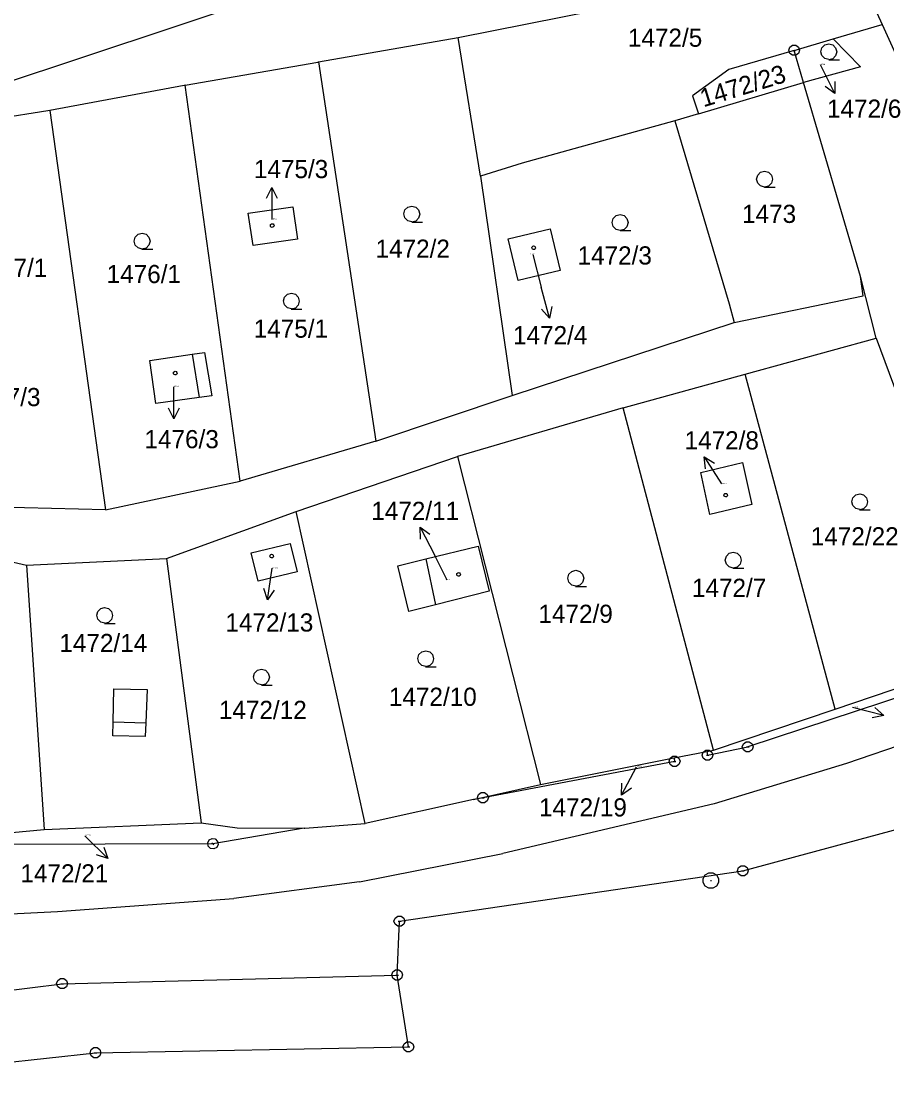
# Model space of a CAD drawing. Extents: x -806774 to -803680, y -1151731 to -1150053.
# Drawn here: x -805196.8 to -805115.9, y -1150674.1 to -1150574.5 of the extents above; entities that cross this region are included whole.
import ezdxf

# ---------------------------------------------------------------- set-up
doc = ezdxf.new("R2010")
doc.units = 0
for name, color, linetype in [('1', 7, 'Continuous'), ('12', 7, 'Continuous'), ('2', 7, 'Continuous'), ('3', 7, 'Continuous'), ('4', 7, 'Continuous'), ('5', 7, 'Continuous'), ('6', 7, 'Continuous'), ('7', 7, 'Continuous'), ('8', 7, 'Continuous')]:
    doc.layers.add(name, color=color, linetype=linetype)

msp = doc.modelspace()

# ---------------------------------------------------------------- linework, layer by layer
at = {"layer": '1'}
for p, q in [((-805123.35, -1150559.31), (-805116.35, -1150574.79)), ((-805156, -1150576), (-805143.08, -1150573.46)), ((-805120.93, -1150576.14), (-805116.35, -1150574.79)), ((-805116.35, -1150574.79), (-805108.82, -1150591.44)), ((-805169.07, -1150578.3), (-805156, -1150576)), ((-805153.92, -1150588.97), (-805156, -1150576)), ((-805124.58, -1150577.22), (-805120.93, -1150576.14)), ((-805120.93, -1150576.14), (-805118.36, -1150578.76)), ((-805124.58, -1150577.22), (-805130.69, -1150579.02)), ((-805123.7, -1150580.21), (-805124.58, -1150577.22)), ((-805181.51, -1150580.47), (-805169.12, -1150578.31)), ((-805169.12, -1150578.31), (-805169.07, -1150578.3)), ((-805169.07, -1150578.3), (-805163.68, -1150613.78)), ((-805130.69, -1150579.02), (-805134.09, -1150581.46)), ((-805118.36, -1150578.76), (-805123.7, -1150580.21)), ((-805181.63, -1150580.5), (-805194.17, -1150582.84)), ((-805181.51, -1150580.47), (-805181.63, -1150580.5)), ((-805176.39, -1150617.53), (-805181.51, -1150580.47)), ((-805133.51, -1150583.16), (-805123.7, -1150580.21)), ((-805118.39, -1150598.36), (-805123.7, -1150580.21)), ((-805134.09, -1150581.46), (-805133.51, -1150583.16)), ((-805194.37, -1150582.88), (-805206.79, -1150584.83)), ((-805194.17, -1150582.84), (-805194.37, -1150582.88)), ((-805194.17, -1150582.84), (-805188.96, -1150620.19)), ((-805133.51, -1150583.16), (-805135.74, -1150583.81)), ((-805135.74, -1150583.81), (-805150, -1150587.78)), ((-805135.74, -1150583.81), (-805130.67, -1150600.93)), ((-805150, -1150587.78), (-805153.92, -1150588.97)), ((-805153.92, -1150588.97), (-805150.96, -1150609.51)), ((-805175.62, -1150592.44), (-805171.46, -1150591.84)), ((-805171.46, -1150591.84), (-805171.01, -1150594.89)), ((-805175.17, -1150595.46), (-805175.62, -1150592.44)), ((-805151.32, -1150594.85), (-805147.39, -1150593.91)), ((-805147.39, -1150593.91), (-805146.46, -1150597.81)), ((-805171.01, -1150594.89), (-805175.17, -1150595.46)), ((-805150.39, -1150598.75), (-805151.32, -1150594.85)), ((-805146.46, -1150597.81), (-805150.39, -1150598.75)), ((-805118.12, -1150600.19), (-805118.39, -1150598.36)), ((-805116.91, -1150604.14), (-805118.39, -1150598.36)), ((-805130.67, -1150600.93), (-805130.18, -1150602.69)), ((-805130.18, -1150602.69), (-805118.12, -1150600.19)), ((-805150.96, -1150609.51), (-805130.18, -1150602.69)), ((-805129.15, -1150607.51), (-805116.91, -1150604.14)), ((-805116.91, -1150604.14), (-805113.43, -1150613.57)), ((-805184.82, -1150606.24), (-805180.87, -1150605.65)), ((-805180.87, -1150605.65), (-805179.73, -1150605.48)), ((-805179.73, -1150605.48), (-805179.03, -1150609.54)), ((-805184.28, -1150610.26), (-805184.82, -1150606.24)), ((-805140.56, -1150610.66), (-805129.15, -1150607.51)), ((-805120.75, -1150638.84), (-805129.15, -1150607.51)), ((-805180.2, -1150609.7), (-805184.28, -1150610.26)), ((-805179.03, -1150609.54), (-805180.2, -1150609.7)), ((-805163.68, -1150613.78), (-805150.96, -1150609.51)), ((-805140.56, -1150610.66), (-805156.07, -1150615.2)), ((-805132.12, -1150642.68), (-805140.56, -1150610.66)), ((-805163.68, -1150613.78), (-805176.39, -1150617.53)), ((-805171.14, -1150620.35), (-805156.07, -1150615.2)), ((-805156.07, -1150615.2), (-805148.29, -1150645.9)), ((-805133.32, -1150616.71), (-805129.41, -1150615.78)), ((-805129.41, -1150615.78), (-805128.54, -1150619.71)), ((-805132.45, -1150620.65), (-805133.32, -1150616.71)), ((-805188.96, -1150620.19), (-805176.39, -1150617.53)), ((-805188.96, -1150620.19), (-805202.04, -1150619.89)), ((-805128.54, -1150619.71), (-805132.45, -1150620.65)), ((-805183.26, -1150624.76), (-805171.14, -1150620.35)), ((-805164.69, -1150649.54), (-805171.14, -1150620.35)), ((-805209.21, -1150622.35), (-805196.37, -1150625.39)), ((-805175.35, -1150624.23), (-805171.71, -1150623.34)), ((-805171.71, -1150623.34), (-805171.06, -1150625.99)), ((-805159.01, -1150624.79), (-805154.14, -1150623.59)), ((-805154.14, -1150623.59), (-805153.1, -1150627.82)), ((-805196.37, -1150625.39), (-805183.26, -1150624.76)), ((-805183.26, -1150624.76), (-805180.04, -1150649.49)), ((-805174.7, -1150626.88), (-805175.35, -1150624.23)), ((-805161.65, -1150625.43), (-805159.01, -1150624.79)), ((-805196.37, -1150625.39), (-805194.7, -1150650.11)), ((-805171.06, -1150625.99), (-805174.7, -1150626.88)), ((-805160.61, -1150629.72), (-805161.65, -1150625.43)), ((-805153.1, -1150627.82), (-805158.11, -1150629.09)), ((-805158.11, -1150629.09), (-805160.61, -1150629.72)), ((-805105.89, -1150634.79), (-805128.92, -1150642.38)), ((-805120.75, -1150638.84), (-805107.03, -1150634.2)), ((-805132.12, -1150642.68), (-805120.75, -1150638.84)), ((-805135.82, -1150643.41), (-805132.75, -1150642.8)), ((-805132.75, -1150642.8), (-805132.12, -1150642.68)), ((-805132.75, -1150642.8), (-805132.67, -1150643.17)), ((-805132.67, -1150643.17), (-805128.92, -1150642.38)), ((-805135.75, -1150643.74), (-805153.67, -1150647.14)), ((-805148.29, -1150645.9), (-805135.82, -1150643.41)), ((-805135.82, -1150643.41), (-805135.75, -1150643.74)), ((-805154.57, -1150647.29), (-805148.29, -1150645.9)), ((-805154.57, -1150647.29), (-805164.69, -1150649.54)), ((-805153.67, -1150647.14), (-805154.57, -1150647.29)), ((-805129.38, -1150653.98), (-805107.63, -1150648.08)), ((-805194.7, -1150650.11), (-805180.04, -1150649.49)), ((-805180.04, -1150649.49), (-805176.67, -1150649.94)), ((-805170.32, -1150649.99), (-805164.69, -1150649.54)), ((-805209.44, -1150651.45), (-805194.7, -1150650.11)), ((-805170.38, -1150650), (-805178.93, -1150651.45)), ((-805176.67, -1150649.94), (-805170.38, -1150650)), ((-805170.38, -1150650), (-805170.32, -1150649.99)), ((-805178.93, -1150651.45), (-805208.17, -1150651.53)), ((-805161.49, -1150658.69), (-805129.38, -1150653.98)), ((-805161.69, -1150663.73), (-805161.49, -1150658.69)), ((-805193.03, -1150664.54), (-805161.69, -1150663.73)), ((-805160.65, -1150670.45), (-805161.69, -1150663.73)), ((-805220.59, -1150668.04), (-805193.03, -1150664.54)), ((-805189.9, -1150671), (-805160.65, -1150670.45)), ((-805218.5, -1150674.08), (-805189.9, -1150671))]:
    msp.add_line(p, q, dxfattribs=at)
at = {"layer": '12'}
for p, q in [((-805175.62, -1150592.44), (-805171.46, -1150591.84)), ((-805171.46, -1150591.84), (-805171.01, -1150594.89)), ((-805175.17, -1150595.46), (-805175.62, -1150592.44)), ((-805151.32, -1150594.85), (-805147.39, -1150593.91)), ((-805147.39, -1150593.91), (-805146.46, -1150597.81)), ((-805171.01, -1150594.89), (-805175.17, -1150595.46)), ((-805150.39, -1150598.75), (-805151.32, -1150594.85)), ((-805146.46, -1150597.81), (-805150.39, -1150598.75)), ((-805184.82, -1150606.24), (-805180.87, -1150605.65)), ((-805180.87, -1150605.65), (-805180.2, -1150609.7)), ((-805184.28, -1150610.26), (-805184.82, -1150606.24)), ((-805180.2, -1150609.7), (-805184.28, -1150610.26)), ((-805133.32, -1150616.71), (-805129.41, -1150615.78)), ((-805129.41, -1150615.78), (-805128.54, -1150619.71)), ((-805132.45, -1150620.65), (-805133.32, -1150616.71)), ((-805128.54, -1150619.71), (-805132.45, -1150620.65)), ((-805175.35, -1150624.23), (-805171.71, -1150623.34)), ((-805171.71, -1150623.34), (-805171.06, -1150625.99)), ((-805159.01, -1150624.79), (-805154.14, -1150623.59)), ((-805154.14, -1150623.59), (-805153.1, -1150627.82)), ((-805174.7, -1150626.88), (-805175.35, -1150624.23)), ((-805159.01, -1150624.79), (-805158.11, -1150629.09)), ((-805171.06, -1150625.99), (-805174.7, -1150626.88)), ((-805153.1, -1150627.82), (-805158.11, -1150629.09))]:
    msp.add_line(p, q, dxfattribs=at)
at = {"layer": '3'}
for points in [[(-805121.33, -1150578.08), (-805121.71, -1150577.98), (-805121.98, -1150577.71), (-805122.08, -1150577.34), (-805121.98, -1150576.97), (-805121.71, -1150576.7), (-805121.34, -1150576.6), (-805120.97, -1150576.7), (-805120.7, -1150576.97), (-805120.6, -1150577.35), (-805120.7, -1150577.73), (-805120.97, -1150578), (-805121.35, -1150578.1), (-805120.35, -1150578.1)], [(-805127.34, -1150590), (-805127.72, -1150589.9), (-805127.99, -1150589.63), (-805128.09, -1150589.26), (-805127.99, -1150588.89), (-805127.72, -1150588.62), (-805127.35, -1150588.52), (-805126.98, -1150588.62), (-805126.71, -1150588.89), (-805126.61, -1150589.27), (-805126.71, -1150589.65), (-805126.98, -1150589.92), (-805127.36, -1150590.02), (-805126.36, -1150590.02)], [(-805160.32, -1150593.26), (-805160.7, -1150593.16), (-805160.97, -1150592.89), (-805161.07, -1150592.52), (-805160.97, -1150592.15), (-805160.7, -1150591.88), (-805160.33, -1150591.78), (-805159.96, -1150591.88), (-805159.69, -1150592.15), (-805159.59, -1150592.53), (-805159.69, -1150592.91), (-805159.96, -1150593.18), (-805160.34, -1150593.28), (-805159.34, -1150593.28)], [(-805140.84, -1150594.06), (-805141.22, -1150593.96), (-805141.49, -1150593.69), (-805141.59, -1150593.32), (-805141.49, -1150592.95), (-805141.22, -1150592.68), (-805140.85, -1150592.58), (-805140.48, -1150592.68), (-805140.21, -1150592.95), (-805140.11, -1150593.33), (-805140.21, -1150593.71), (-805140.48, -1150593.98), (-805140.86, -1150594.08), (-805139.86, -1150594.08)], [(-805185.54, -1150595.8), (-805185.92, -1150595.7), (-805186.19, -1150595.43), (-805186.29, -1150595.06), (-805186.19, -1150594.69), (-805185.92, -1150594.42), (-805185.55, -1150594.32), (-805185.18, -1150594.42), (-805184.91, -1150594.69), (-805184.81, -1150595.07), (-805184.91, -1150595.45), (-805185.18, -1150595.72), (-805185.56, -1150595.82), (-805184.56, -1150595.82)], [(-805171.58, -1150601.4), (-805171.96, -1150601.3), (-805172.23, -1150601.03), (-805172.33, -1150600.66), (-805172.23, -1150600.29), (-805171.96, -1150600.02), (-805171.59, -1150599.92), (-805171.22, -1150600.02), (-805170.95, -1150600.29), (-805170.85, -1150600.67), (-805170.95, -1150601.05), (-805171.22, -1150601.32), (-805171.6, -1150601.42), (-805170.6, -1150601.42)], [(-805118.44, -1150620.18), (-805118.82, -1150620.08), (-805119.09, -1150619.81), (-805119.19, -1150619.44), (-805119.09, -1150619.07), (-805118.82, -1150618.8), (-805118.45, -1150618.7), (-805118.08, -1150618.8), (-805117.81, -1150619.07), (-805117.71, -1150619.45), (-805117.81, -1150619.83), (-805118.08, -1150620.1), (-805118.46, -1150620.2), (-805117.46, -1150620.2)], [(-805130.27, -1150625.65), (-805130.65, -1150625.55), (-805130.92, -1150625.28), (-805131.02, -1150624.91), (-805130.92, -1150624.54), (-805130.65, -1150624.27), (-805130.28, -1150624.17), (-805129.91, -1150624.27), (-805129.64, -1150624.54), (-805129.54, -1150624.92), (-805129.64, -1150625.3), (-805129.91, -1150625.57), (-805130.29, -1150625.67), (-805129.29, -1150625.67)], [(-805144.99, -1150627.34), (-805145.37, -1150627.24), (-805145.64, -1150626.97), (-805145.74, -1150626.6), (-805145.64, -1150626.23), (-805145.37, -1150625.96), (-805145, -1150625.86), (-805144.63, -1150625.96), (-805144.36, -1150626.23), (-805144.26, -1150626.61), (-805144.36, -1150626.99), (-805144.63, -1150627.26), (-805145.01, -1150627.36), (-805144.01, -1150627.36)], [(-805189.04, -1150630.81), (-805189.42, -1150630.71), (-805189.69, -1150630.44), (-805189.79, -1150630.07), (-805189.69, -1150629.7), (-805189.42, -1150629.43), (-805189.05, -1150629.33), (-805188.68, -1150629.43), (-805188.41, -1150629.7), (-805188.31, -1150630.08), (-805188.41, -1150630.46), (-805188.68, -1150630.73), (-805189.06, -1150630.83), (-805188.06, -1150630.83)], [(-805159.02, -1150634.86), (-805159.4, -1150634.76), (-805159.67, -1150634.49), (-805159.77, -1150634.12), (-805159.67, -1150633.75), (-805159.4, -1150633.48), (-805159.03, -1150633.38), (-805158.66, -1150633.48), (-805158.39, -1150633.75), (-805158.29, -1150634.13), (-805158.39, -1150634.51), (-805158.66, -1150634.78), (-805159.04, -1150634.88), (-805158.04, -1150634.88)], [(-805174.38, -1150636.58), (-805174.76, -1150636.48), (-805175.03, -1150636.21), (-805175.13, -1150635.84), (-805175.03, -1150635.47), (-805174.76, -1150635.2), (-805174.39, -1150635.1), (-805174.02, -1150635.2), (-805173.75, -1150635.47), (-805173.65, -1150635.85), (-805173.75, -1150636.23), (-805174.02, -1150636.5), (-805174.4, -1150636.6), (-805173.4, -1150636.6)]]:
    msp.add_lwpolyline(points, dxfattribs=at)
at = {"layer": '4'}
for p, q in [((-805180.87, -1150605.65), (-805180.2, -1150609.7)), ((-805159.01, -1150624.79), (-805158.11, -1150629.09)), ((-805188.25, -1150640.05), (-805188.19, -1150636.96)), ((-805188.19, -1150636.96), (-805185.08, -1150637)), ((-805185.08, -1150637), (-805185.2, -1150640.13)), ((-805188.28, -1150641.34), (-805188.25, -1150640.05)), ((-805188.25, -1150640.05), (-805185.2, -1150640.13)), ((-805185.2, -1150640.13), (-805185.26, -1150641.41)), ((-805185.26, -1150641.41), (-805188.28, -1150641.34))]:
    msp.add_line(p, q, dxfattribs=at)
at = {"layer": '5'}
for points in [[(-805173.38, -1150593.44), (-805173.28, -1150593.46), (-805173.23, -1150593.55), (-805173.21, -1150593.61), (-805173.23, -1150593.7), (-805173.31, -1150593.77), (-805173.38, -1150593.78), (-805173.47, -1150593.75), (-805173.53, -1150593.69), (-805173.55, -1150593.61), (-805173.53, -1150593.52), (-805173.45, -1150593.45)], [(-805148.94, -1150595.51), (-805148.84, -1150595.53), (-805148.79, -1150595.62), (-805148.77, -1150595.68), (-805148.79, -1150595.77), (-805148.87, -1150595.84), (-805148.94, -1150595.85), (-805149.03, -1150595.82), (-805149.09, -1150595.76), (-805149.11, -1150595.68), (-805149.09, -1150595.59), (-805149.01, -1150595.52)], [(-805182.45, -1150607.24), (-805182.35, -1150607.26), (-805182.3, -1150607.35), (-805182.28, -1150607.41), (-805182.3, -1150607.5), (-805182.38, -1150607.57), (-805182.45, -1150607.58), (-805182.54, -1150607.55), (-805182.6, -1150607.49), (-805182.62, -1150607.41), (-805182.6, -1150607.32), (-805182.52, -1150607.25)], [(-805130.98, -1150618.66), (-805130.88, -1150618.68), (-805130.83, -1150618.77), (-805130.81, -1150618.83), (-805130.83, -1150618.92), (-805130.91, -1150618.99), (-805130.98, -1150619), (-805131.07, -1150618.97), (-805131.13, -1150618.91), (-805131.15, -1150618.83), (-805131.13, -1150618.74), (-805131.05, -1150618.67)], [(-805173.44, -1150624.36), (-805173.34, -1150624.38), (-805173.29, -1150624.47), (-805173.27, -1150624.53), (-805173.29, -1150624.62), (-805173.37, -1150624.69), (-805173.44, -1150624.7), (-805173.53, -1150624.67), (-805173.59, -1150624.61), (-805173.61, -1150624.53), (-805173.59, -1150624.44), (-805173.51, -1150624.37)], [(-805155.96, -1150626.08), (-805155.86, -1150626.1), (-805155.81, -1150626.19), (-805155.79, -1150626.25), (-805155.81, -1150626.34), (-805155.89, -1150626.41), (-805155.96, -1150626.42), (-805156.05, -1150626.39), (-805156.11, -1150626.33), (-805156.13, -1150626.25), (-805156.11, -1150626.16), (-805156.03, -1150626.09)]]:
    msp.add_lwpolyline(points, close=True, dxfattribs=at)
at = {"layer": '6'}
for p, q in [((-805267.37, -1150603.37), (-805132.32, -1150558.17)), ((-805104.02, -1150638.5), (-805119.69, -1150643.95)), ((-805119.69, -1150643.95), (-805132.06, -1150647.7)), ((-805132.06, -1150647.7), (-805151.83, -1150652.34)), ((-805165.22, -1150655), (-805151.83, -1150652.34)), ((-805165.22, -1150655), (-805176.96, -1150656.55)), ((-805193.46, -1150657.79), (-805176.96, -1150656.55)), ((-805221.49, -1150659.08), (-805193.46, -1150657.79))]:
    msp.add_line(p, q, dxfattribs=at)
at = {"layer": '7'}
for p, q in [((-805120.779, -1150581.254), (-805122.12, -1150578.57)), ((-805173.42, -1150590.04), (-805173.42, -1150593.04)), ((-805149.02, -1150596.3), (-805148.22, -1150599.38)), ((-805147.468, -1150602.284), (-805148.22, -1150599.38)), ((-805182.579, -1150611.7), (-805182.58, -1150608.7)), ((-805132.996, -1150615.259), (-805131.37, -1150617.78)), ((-805159.537, -1150621.819), (-805158.17, -1150624.49)), ((-805157.01, -1150626.78), (-805158.17, -1150624.49)), ((-805173.834, -1150628.637), (-805173.39, -1150625.67)), ((-805116.2, -1150639.429), (-805119.11, -1150638.7)), ((-805140.713, -1150646.902), (-805139.31, -1150644.25)), ((-805188.769, -1150652.821), (-805190.89, -1150650.7))]:
    msp.add_line(p, q, dxfattribs=at)
for points in [[(-805120.779, -1150580.136), (-805120.779, -1150581.254), (-805121.673, -1150580.583)], [(-805173.92, -1150591.04), (-805173.42, -1150590.04), (-805172.92, -1150591.04)], [(-805147.235, -1150601.191), (-805147.468, -1150602.284), (-805148.203, -1150601.441)], [(-805182.079, -1150610.7), (-805182.579, -1150611.7), (-805183.079, -1150610.7)], [(-805132.874, -1150616.371), (-805132.996, -1150615.259), (-805132.034, -1150615.828)], [(-805159.526, -1150622.937), (-805159.537, -1150621.819), (-805158.636, -1150622.482)], [(-805173.192, -1150627.722), (-805173.834, -1150628.637), (-805174.181, -1150627.574)], [(-805117.048, -1150638.701), (-805116.2, -1150639.429), (-805117.291, -1150639.671)], [(-805139.803, -1150646.252), (-805140.713, -1150646.902), (-805140.687, -1150645.784)], [(-805189.122, -1150651.761), (-805188.769, -1150652.821), (-805189.829, -1150652.468)]]:
    msp.add_lwpolyline(points, dxfattribs=at)
at = {"layer": '8'}
for p, q in [((-805124.7, -1150577.22), (-805124.46, -1150577.22)), ((-805129.04, -1150642.38), (-805128.8, -1150642.38)), ((-805135.87, -1150643.74), (-805135.63, -1150643.74)), ((-805132.79, -1150643.17), (-805132.55, -1150643.17)), ((-805153.79, -1150647.14), (-805153.55, -1150647.14)), ((-805179.015, -1150651.365), (-805178.845, -1150651.535)), ((-805132.41, -1150654.87), (-805132.31, -1150654.87)), ((-805129.5, -1150653.98), (-805129.26, -1150653.98)), ((-805161.61, -1150658.69), (-805161.37, -1150658.69)), ((-805161.81, -1150663.73), (-805161.57, -1150663.73)), ((-805193.15, -1150664.54), (-805192.91, -1150664.54)), ((-805160.77, -1150670.45), (-805160.53, -1150670.45)), ((-805190.02, -1150671), (-805189.78, -1150671))]:
    msp.add_line(p, q, dxfattribs=at)
for points in [[(-805124.43, -1150576.74), (-805124.18, -1150576.92), (-805124.08, -1150577.21), (-805124.18, -1150577.5), (-805124.43, -1150577.68), (-805124.74, -1150577.68), (-805124.99, -1150577.5), (-805125.09, -1150577.21), (-805124.99, -1150576.92), (-805124.74, -1150576.74)], [(-805128.77, -1150641.9), (-805128.52, -1150642.08), (-805128.42, -1150642.37), (-805128.52, -1150642.66), (-805128.77, -1150642.84), (-805129.08, -1150642.84), (-805129.33, -1150642.66), (-805129.43, -1150642.37), (-805129.33, -1150642.08), (-805129.08, -1150641.9)], [(-805132.52, -1150642.69), (-805132.27, -1150642.87), (-805132.17, -1150643.16), (-805132.27, -1150643.45), (-805132.52, -1150643.63), (-805132.83, -1150643.63), (-805133.08, -1150643.45), (-805133.18, -1150643.16), (-805133.08, -1150642.87), (-805132.83, -1150642.69)], [(-805135.6, -1150643.26), (-805135.35, -1150643.44), (-805135.25, -1150643.73), (-805135.35, -1150644.02), (-805135.6, -1150644.2), (-805135.91, -1150644.2), (-805136.16, -1150644.02), (-805136.26, -1150643.73), (-805136.16, -1150643.44), (-805135.91, -1150643.26)], [(-805153.52, -1150646.66), (-805153.27, -1150646.84), (-805153.17, -1150647.13), (-805153.27, -1150647.42), (-805153.52, -1150647.6), (-805153.83, -1150647.6), (-805154.08, -1150647.42), (-805154.18, -1150647.13), (-805154.08, -1150646.84), (-805153.83, -1150646.66)], [(-805178.485, -1150651.217), (-805178.435, -1150651.521), (-805178.569, -1150651.796), (-805178.845, -1150651.931), (-805179.149, -1150651.881), (-805179.368, -1150651.662), (-805179.418, -1150651.358), (-805179.284, -1150651.082), (-805179.008, -1150650.948), (-805178.704, -1150650.997)], [(-805129.23, -1150653.5), (-805128.98, -1150653.68), (-805128.88, -1150653.97), (-805128.98, -1150654.26), (-805129.23, -1150654.44), (-805129.54, -1150654.44), (-805129.79, -1150654.26), (-805129.89, -1150653.97), (-805129.79, -1150653.68), (-805129.54, -1150653.5)], [(-805132.17, -1150654.15), (-805131.83, -1150654.34), (-805131.64, -1150654.68), (-805131.64, -1150655.07), (-805131.83, -1150655.41), (-805132.17, -1150655.6), (-805132.56, -1150655.6), (-805132.9, -1150655.41), (-805133.09, -1150655.07), (-805133.09, -1150654.68), (-805132.9, -1150654.34), (-805132.56, -1150654.15)], [(-805161.34, -1150658.21), (-805161.09, -1150658.39), (-805160.99, -1150658.68), (-805161.09, -1150658.97), (-805161.34, -1150659.15), (-805161.65, -1150659.15), (-805161.9, -1150658.97), (-805162, -1150658.68), (-805161.9, -1150658.39), (-805161.65, -1150658.21)], [(-805161.54, -1150663.25), (-805161.29, -1150663.43), (-805161.19, -1150663.72), (-805161.29, -1150664.01), (-805161.54, -1150664.19), (-805161.85, -1150664.19), (-805162.1, -1150664.01), (-805162.2, -1150663.72), (-805162.1, -1150663.43), (-805161.85, -1150663.25)], [(-805192.88, -1150664.06), (-805192.63, -1150664.24), (-805192.53, -1150664.53), (-805192.63, -1150664.82), (-805192.88, -1150665), (-805193.19, -1150665), (-805193.44, -1150664.82), (-805193.54, -1150664.53), (-805193.44, -1150664.24), (-805193.19, -1150664.06)], [(-805189.75, -1150670.52), (-805189.5, -1150670.7), (-805189.4, -1150670.99), (-805189.5, -1150671.28), (-805189.75, -1150671.46), (-805190.06, -1150671.46), (-805190.31, -1150671.28), (-805190.41, -1150670.99), (-805190.31, -1150670.7), (-805190.06, -1150670.52)], [(-805160.5, -1150669.97), (-805160.25, -1150670.15), (-805160.15, -1150670.44), (-805160.25, -1150670.73), (-805160.5, -1150670.91), (-805160.81, -1150670.91), (-805161.06, -1150670.73), (-805161.16, -1150670.44), (-805161.06, -1150670.15), (-805160.81, -1150669.97)]]:
    msp.add_lwpolyline(points, close=True, dxfattribs=at)

# ---------------------------------------------------------------- texts
at = {"layer": '2'}
for s, height, p in [('1472/5', 1.7, (-805140.125, -1150576.88)), ('1472/6', 0.1, (-805122.097, -1150578.57)), ('1473', 1.7, (-805129.452, -1150593.36)), ('1475/3', 0.1, (-805173.397, -1150593.04)), ('1472/2', 1.7, (-805163.722, -1150596.62)), ('1472/3', 1.7, (-805144.835, -1150597.25)), ('1477/1', 1.7, (-805201.366, -1150598.41)), ('1472/4', 0.1, (-805149.244, -1150596.3)), ('1476/1', 1.7, (-805188.866, -1150598.99)), ('1475/1', 1.7, (-805175.113, -1150604.1)), ('1476/3', 0.1, (-805182.557, -1150608.7)), ('1472/8', 0.1, (-805131.347, -1150617.78)), ('1472/22', 1.7, (-805123.024, -1150623.53)), ('1472/13', 0.1, (-805173.367, -1150625.67)), ('1472/11', 0.1, (-805157.234, -1150626.78)), ('1472/7', 1.7, (-805134.138, -1150628.35)), ('1472/9', 1.7, (-805148.488, -1150630.78)), ('1472/14', 1.7, (-805193.289, -1150633.51)), ('1472/10', 1.7, (-805162.476, -1150638.54)), ('1472/12', 1.7, (-805178.373, -1150639.77)), ('1472/20', 0.1, (-805119.087, -1150638.7)), ('1472/19', 0.1, (-805139.287, -1150644.25)), ('1472/21', 0.1, (-805190.867, -1150650.7))]:
    msp.add_text(s, height=height, dxfattribs=at).set_placement(p)
msp.add_text('1472/23', height=1.7, rotation=17.07414, dxfattribs=at).set_placement((-805133.063, -1150582.55))
at = {"layer": '7'}
for s, p in [('1472/6', (-805121.507, -1150583.52)), ('1475/3', (-805175.097, -1150589.17)), ('1472/4', (-805150.868, -1150604.71)), ('1477/3', (-805202.001, -1150610.5)), ('1476/3', (-805185.327, -1150614.44)), ('1472/8', (-805134.827, -1150614.55)), ('1472/11', (-805164.121, -1150621.15)), ('1472/13', (-805177.757, -1150631.59)), ('1472/19', (-805148.437, -1150648.89)), ('1472/21', (-805196.924, -1150655.06))]:
    msp.add_text(s, height=1.7, dxfattribs=at).set_placement(p)

doc.saveas('drawing.dxf')
